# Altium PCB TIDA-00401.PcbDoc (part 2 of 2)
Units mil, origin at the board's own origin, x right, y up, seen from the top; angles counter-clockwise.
Board outline 3543.31 x 2362.2 mil, 2 copper layers (Top Layer, Bottom Layer), stack 62 mil thick; 132 components, 43 nets, 274 pads, 44 vias.
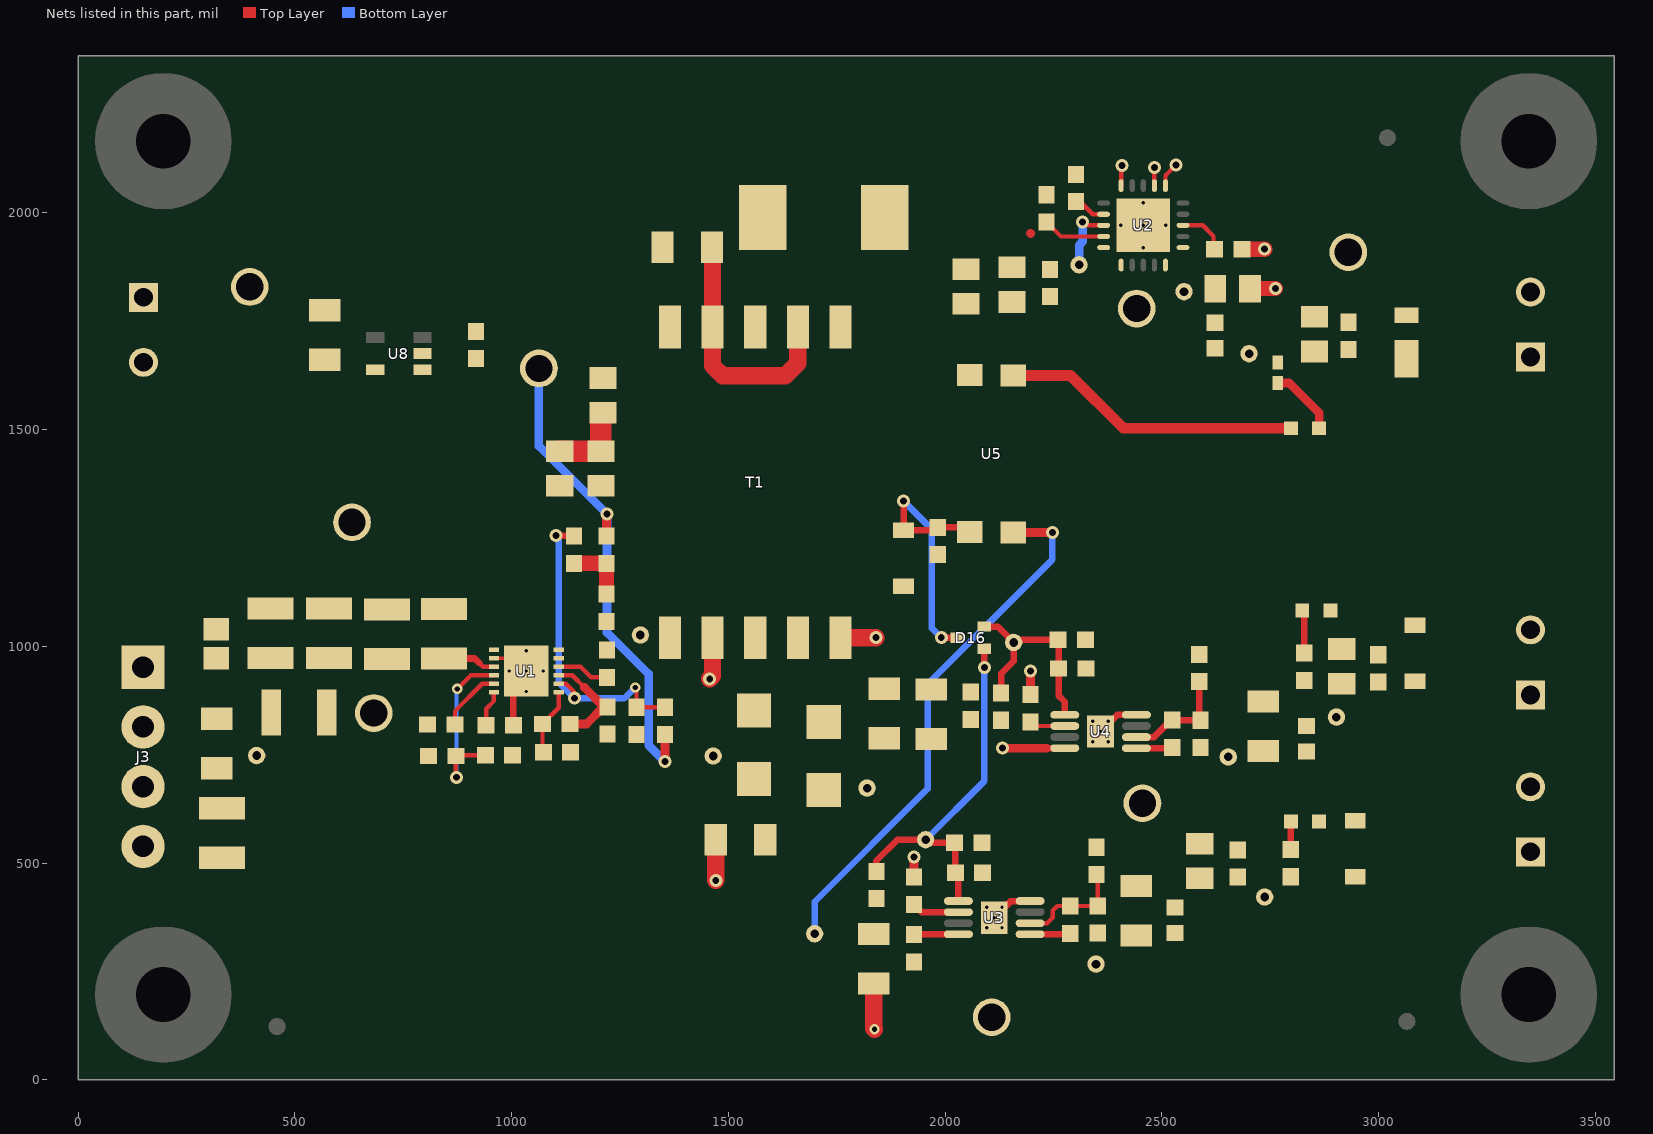
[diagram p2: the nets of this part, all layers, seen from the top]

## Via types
v1: diameter 30, hole 16, Top Layer to Bottom Layer, tented both sides, 21 vias
v2: diameter 19.68, hole 7.87, Top Layer to Bottom Layer, tented both sides, 20 vias
v3: diameter 24, hole 12, Top Layer to Bottom Layer, tented both sides, 3 vias

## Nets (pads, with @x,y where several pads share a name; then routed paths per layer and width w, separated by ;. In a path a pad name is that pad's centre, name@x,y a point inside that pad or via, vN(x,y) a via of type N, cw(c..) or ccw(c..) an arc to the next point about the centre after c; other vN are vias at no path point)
9V_NON_ISO: C6.2 C47.1 R5.2 R7.2 T1.10 TP11.1 U8.1 | length 1141
  Top Layer w20: C6.2@1219,1254.5 1219,1299 1220,1300 v1(1220,1305) ; v1(1354,734) R7.2@1354,796.5
  Bottom Layer w20: TP11.1@1063,1641 1063,1462 v1(1220,1305) 1220,1032 1316,936 1316,772 v1(1354,734)
15GND: C1.1 C2.1 C27.1 C28.1 C29.2 C30.1 C31.2 C32.2 C33.2 C35.1 C36.1 C37.2 C38.1 C39.2 C40.2 C41.2 D6.2 D7.1 D8.1 D9.2 D15.2 J5.2 J6.2 R15.2 R16.1 R20.2 R26.2 R27.1 T1.2 T1.5 TP2.1 TP4.1 TP5.1 U3.4 U3.9 U4.4 U4.9 | length 677.2
  Top Layer w15: v2(2113.32,374.2) 2151.71,412.59 U3.4@2196,412.59 ; v2(2358.54,803.49) 2396.93,841.88 U4.4@2441.22,841.88
  Top Layer w20: C33.2@1928,467.5 v1(1928,514) ; C41.2@2197,888.5 v1(2197,943)
  Top Layer w40: v1(1457,925) 1463.43,931.43 T1.2@1463.43,1020 ; v1(1470.91,460.09) C1.1@1470.91,554 ; T1.5@1758.7,1020 v1(1840,1020) ; C31.2@1835.32,222.43 1835.32,118.68 v3(1837,117)
  other v2: 2095.61,350.58 2131.04,350.58 2095.61,397.83 2131.04,397.83 2340.83,779.87 2376.26,779.87 2340.83,827.11 2376.26,827.11
+5V_ISO: C21.1 C45.2 D24.1 J4.1 L2.2 R21.1 TP16.1
+6V_ISO: C4.1 C44.1 C46.2 D3.1 TP6.1 U2.13 U2.15 U2.16 | length 154.1
  Top Layer w10: v1(2317,1979) 2325,1971 U2.13@2365.46,1971
  Bottom Layer w20: TP6.1@2309,1880 2309,1925 2317,1933 v1(2317,1979)
+15V_ISO: C27.2 C28.2 D6.1 J5.1 L3.2 R14.1 TP17.1
+18V_ISO: C1.2 C30.2 C31.1 D1.1 R23.2 TP1.1 U3.8 U5.4 | length 1345.6
  Top Layer w10: C30.2@1928.32,335.02 C30.2@1929.13,335.82
  Top Layer w15: C30.2@1929.13,335.82 U3.8@2030.65,335.82
  Top Layer w20: U5.4@2157,1262.41 v1(2247.41,1262.41)
  Bottom Layer w15: TP1.1@1699,337 1699,411 1960,672 1960,913 2247.41,1200.41 v1(2247.41,1262.41)
+24VDC: C16.1 C17.1 F1.1 L1.1 RV1.2 TP14.1
-15V_ISO: C35.2 C36.2 D8.2 J6.1 L4.2 R24.1 TP22.1
-18V_ISO: C2.2 C38.2 C39.1 D2.2 R17.2 TP3.1 U4.8 | length 144
  Top Layer w15: 2234.57,765.11 U4.8@2275.87,765.11
  Top Layer w20: v1(2131.89,765.11) 2234.57,765.11
BST: C5.2 U1.10 | length 121.5
  Top Layer w10: U1.10@1108.8,952.84 1159.16,952.84 1183.58,928.42 C5.2@1220.2,928.42
"CO PRI": C14.1 C15.1 R5.1 | length 186.1
  Top Layer w50: C15.1@1111,1450 C14.1@1206,1450 1206,1534 R5.1@1211,1539
EN: R3.1 R9.2 U1.4 | length 420.4
  Top Layer w10: v1(873,698) 871.5,699.5 R3.1@871.5,747 873.5,749 R9.2@939.5,749 ; v3(874.68,901.72) 906.12,933.16 U1.4@959.2,933.16
  Bottom Layer w10: v1(873,698) 873,900.04 v3(874.68,901.72)
EN_15V: C29.1 D16.1 R23.1 R27.2 TP26.1 U3.5 | length 862.3
  Top Layer w15: R23.1@1841.32,481.02 1841.32,505.32 1890,554 TP26.1@1955,554 1962,547 C29.1@2021.5,547 2023.5,545 R27.2@2023.5,478 2030.65,470.86 U3.5@2030.65,412.59 ; v1(2090.5,951.5) D16.1@2090.5,994.41
  Bottom Layer w15: TP26.1@1955,554 2090.5,689.5 v1(2090.5,951.5)
EN_-15V: C37.1 D16.2 R16.2 R17.1 TP25.1 U4.5 | length 495.7
  Top Layer w15: D16.2@2090.5,1045.59 2121.41,1045.59 TP25.1@2158,1009 ; R17.1@2129,892.5 2129,937 2158,966 TP25.1@2158,1009 ; U4.5@2275.87,841.88 2275.87,872.13 2261.5,886.5 R16.2@2261.5,949 2261.5,1014 C37.1@2260.5,1015 2164,1015 TP25.1@2158,1009
FB: C8.2 R7.1 R8.2 U1.8 | length 753.3
  Top Layer w10: U1.8@1108.8,913.47 1125.65,913.47 1144,895.12 1144,880.92 v1(1144.61,880.3) ; v3(1285,905) 1288,902 R8.2@1288,859.5 R7.1@1354,859.5
  Top Layer w15: v1@1103.5,1254.5 C8.2@1144,1254.5
  Bottom Layer w15: v1@1099,1253 1109,1243 1109,915.92 v1(1144.61,880.3) 1260.3,880.3 v3(1285,905)
  other v1: 1102,1256
FPWM: R4.2 R10.2 U1.7 | length 154.3
  Top Layer w10: R10.2@1073.31,755.84 1071.31,757.84 R4.2@1071.31,820.84 1108.8,858.34 U1.7@1108.8,893.79
GND: C3.2 C7.2 C11.2 C12.2 C13.2 C14.2 C15.2 C16.2 C17.2 C18.2 C42.1 C47.2 J2.1 J3.1 J3.2 R8.1 R9.1 R10.1 RV1.1 TP12.1 TP13.1 U1.1 U1.2 U1.13 U8.2 | length 224.5
  Top Layer w8: U1.2@959.2,972.53 1004.47,972.53 v2(1034,943)
  Top Layer w15: C7.2@1004.3,817.84 1004.3,913.3 v2(1034,943)
  other v2: 1034,895.76 994.63,943 1073.37,943 1034,990.24
NetC19_2: C19.2 C20.1 L2.1 TP15.1 U2.1 U2.3 U2.20 | length 111.9
  Top Layer w10: U2.3@2548.54,1971 2594,1971 2619,1946 2619,1918.5 C19.2@2621.5,1916
NetC25_1: C25.1 U2.14 | length 145.2
  Top Layer w10: C25.1@2234,1978.5 2267.09,1945.41 U2.14@2365.46,1945.41
NetC26_1: C26.1 C32.1 L3.1 R25.1 TP18.1 U3.1 | length 93.2
  Top Layer w15: U3.1@2196,335.82 2286.12,335.82 C26.1@2288.32,338.02
NetC26_2: C26.2 R25.2 R26.1 U3.2 | length 271.7
  Top Layer w10: U3.2@2196,361.41 2235.21,361.41 2248.32,374.52 2248.32,390.79 2258.55,401.02 C26.2@2288.32,401.02 R25.2@2343.48,401.02 ; R26.1@2349,473.5 2352,470.5 R26.1@2352,459.5 ; R26.1@2351,460.5 R26.1@2352,459.5 ; R25.2@2353,391.5 R25.2@2343.48,401.02 ; R26.1@2353,458.5 R26.1@2352,459.5 ; R25.2@2343.48,401.02 2351.52,401.02 R25.2@2352,401.5 R26.1@2352,459.5
NetC33_1: C33.1 U3.6 | length 109.9
  Top Layer w15: C33.1@1928,404.5 1945.5,387 U3.6@2030.65,387
NetC34_1: C34.1 C40.1 L4.1 R19.1 TP20.1 U4.1 | length 83.1
  Top Layer w15: U4.1@2441.22,765.11 2521.66,765.11 C34.1@2523.54,766.99
NetC34_2: C34.2 R19.2 R20.1 U4.2 | length 253.8
  Top Layer w15: U4.2@2441.22,790.7 2481.7,790.7 2520.98,829.98 C34.2@2523.54,829.98 R19.2@2588.51,829.98 ; R20.1@2586,918.5 2586,832.5 R19.2@2588.51,829.98 ; R19.2@2589,829.5 R19.2@2588.51,829.98
NetC41_1: C41.1 U4.6 | length 82.7
  Top Layer w10: C41.1@2197,825.5 2206.22,816.29 U4.6@2275.87,816.29
NetC42_2: C42.2 J2.2 U8.5
NetD1_2: D1.2 T1.3
NetD2_1: D2.1 T1.4
NetD3_2: D3.2 T1.6 T1.8
NetD5_1: D5.1 U5.1 | length 690.9
  Top Layer w25: U5.1@2157,1624.61 2289.39,1624.61 2411,1503 D5.1@2797.52,1503
NetD5_2: D5.2 R21.2 | length 159.7
  Top Layer w20: R21.2@2767,1607.38 2793.94,1607.38 2862.48,1538.84 D5.2@2862.48,1503
NetD7_2: D7.2 R14.2 | length 65.1
  Top Layer w15: R14.2@2797,531.5 2797,594.48 D7.2@2798.52,596
NetD9_1: D9.1 R24.2 | length 100.4
  Top Layer w15: D9.1@2823.52,1083 2828,1078.52 R24.2@2828,984.5
NetD15_1: D15.1 D16.3 R15.1 U5.3 | length 615.6
  Top Layer w15: v1(1904,1335) D15.1@1904,1267.47 1975.97,1267.47 R15.1@1983,1274.5 2045.89,1274.5 U5.3@2057,1263.39 ; v1(1991,1020) D16.3@2027.5,1020
  Bottom Layer w15: v1(1904,1335) 1969.5,1269.5 1969.5,1041.5 v1(1991,1020)
NetF1_2: F1.2 J3.3 J3.4
NetR22_1: R22.1 U2.12 | length 75.4
  Top Layer w10: R22.1@2302,2025.5 2311.51,2025.5 2340.42,1996.59 U2.12@2365.46,1996.59
RON: R2.1 U1.5 | length 146.3
  Top Layer w10: R2.1@869.5,820 869.5,850.5 932.47,913.47 U1.5@959.2,913.47
SGND: C3.1 C4.2 C19.1 C20.2 C21.2 C25.2 C44.2 C45.1 C46.1 D24.2 J4.2 R22.2 T1.7 T1.9 TP7.1 TP8.1 U2.6 U2.7 U2.10 U2.21 U5.2 | length 833.8
  Top Layer w10: U2.10@2405.82,2062.54 2405.82,2106.82 v1(2408,2109) ; U2.7@2482.59,2062.54 v1(2482.59,2104.41) ; U2.6@2508.18,2062.54 2508.18,2086.18 v1(2532,2110)
  Top Layer w20: 2197,1952.5 2197.5,1952
  Top Layer w35: C19.1@2684.5,1916 v1(2737,1916) ; C20.2@2703,1825 v1(2762,1825)
  Top Layer w40: C3.1@1462.09,1920 1463.43,1918.66 T1.9@1463.43,1736.54 1463.43,1647.57 1487,1624 1631,1624 1660.28,1653.28 T1.7@1660.28,1736.54
  other v2: 2457,1918.83 2404.83,1971 2457,1971 2509.17,1971 2457,2023.17
SS: C7.1 U1.6 | length 83.4
  Top Layer w10: C7.1@941.31,817.84 941.31,855.95 959.2,873.84 U1.6@959.2,893.79
VCC: C13.1 R4.1 U1.9 | length 228.4
  Top Layer w10: U1.9@1108.8,933.16 1139.84,933.16 1168,905
  Top Layer w20: R4.1@1134.3,820.84 1172.85,820.84 1212.5,860.5 1168,905
VIN: C11.1 C12.1 C18.1 L1.2 R2.2 R3.2 TP10.1 U1.3 | length 123.1
  Top Layer w10: 926,961 934.16,952.84 U1.3@959.2,952.84
  Top Layer w15: C12.1@844,971.91 915.09,971.91 926,961
VRIPL: C6.1 C8.1 R6.2 | length 146
  Top Layer w35: C8.1@1144,1191.5 C6.1@1219,1191.5 R6.2@1219,1120.5
"VSW PRI": C5.1 R6.1 T1.1 TP9.1 U1.11 U1.12
pads on no net: FID1.1 FID2.1 FID3.1 H1.1 H2.1 H3.1 H4.1 LBL1.0 U2.2 U2.4 U2.5 U2.8 U2.9 U2.11 U2.17 U2.18 U2.19 U3.3 U3.7 U4.3 U4.7 U8.3 U8.4

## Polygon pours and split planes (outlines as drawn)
-15V_ISO on Top Layer "Top Layer--15V_ISO" (solid, remove dead copper, pour order 49): 2798,936 2798,814 2814,798 2937,798 2976,837 3394,837 3404,847 3404,934 3397,941 2803,941
NetC42_2 on Top Layer "Top Layer-NetC42_2" (solid, remove dead copper, pour order 31): 99.5,1683 100,1634 108,1625 704,1625 706,1627 706,1691 704,1693 109.5,1693
9V_NON_ISO on Top Layer "Top Layer-VIN" (solid, remove dead copper, pour order 54): 775,1651 773,1649 773,1628 775,1626 836,1626 868,1594 1375,1594 1394,1613 1394,1784 1392,1786 1339,1786 1336,1783 1336,1697 1323,1684 869,1684 836,1651
NetD2_1 on Top Layer "Top Layer-NetD2_1" (solid, remove dead copper, pour order 41): 1635,1068 1635,823 1672,786 1777,786 1796,805 1796,899 1763,932 1695,932 1686,941 1686,1068 1684,1070 1637,1070
NetD1_2 on Top Layer "Top Layer-NetD1_2" (solid, remove dead copper, pour order 40): 1536,1068 1536,919 1510,893 1510,818 1520,808 1610,808 1616,814 1616,881 1595,902 1595,964 1587,973 1587,1068 1585,1070 1538,1070
"VSW PRI" on Top Layer "Top Layer-VSW PRI" (solid, remove dead copper, pour order 32): 1155,1000 1185,1030 1185,1069 1193,1077 1302,1077 1309,1070 1389,1070 1391,1068 1391,969 1390,968 1256,968 1252,972 1127,972 1122,967 1096,967 1095,968 1095,999 1096,1000
NetD3_2 on Top Layer "Top Layer-NetD3_2" (solid, remove dead copper, pour order 38): 1526,2078 1524,2076 1524,1912 1537,1899 1537,1830 1536,1829 1536,1689 1538,1687 1586,1687 1588,1689 1588,1833 1605,1850 1729,1850 1732,1847 1732,1692 1736,1688 1783,1688 1785,1690 1785,1871 1740,1916 1662,1916 1650,1928 1650,2060 1632,2078
GND on Top Layer "Bottom Layer-No Net" (solid, remove dead copper, pour order 28): 1357,1869 1373.78,1885.83 1373.78,2006.26 1352.28,2027.76 1198.28,2027.76 1178.78,2008.26 1178.78,1901.26 1211,1869
NetD5_1 on Top Layer "Top Layer-NetD5_1" (solid, remove dead copper, pour order 45): 2128,1650 2127,1649 2127,1600 2141,1586 2236,1586 2251,1601 2251,1636 2247,1640 2193,1640 2183,1650
NetF1_2 on Top Layer "Top Layer-NetF1_2" (solid, remove dead copper, pour order 46): 117,733 186,733 197,722 210,709 210,592 210,571 219,562 220,561 306,561 390,561 394,557 396.72,554.28 396.72,500.8 396.72,500.72 396.72,496.72 382,482 378.32,478.32 150,478.32 111.68,478.32 101,489 94,496 94,580 94,725 102,733
+24VDC on Top Layer "Top Layer-+24VDC" (solid, remove dead copper, pour order 52): 289,997 290,998 363,998 492,998 496,994 496,968 496,894.99 487,885.99 487,816 487,773 481,767 434,720 434,649 391,606 386,601 364,601 278,601 272,607 263.28,615.72 263.28,628.49 263.28,641.28 263.28,724.28 283,744 284,745 356,745 365,754 371,760 371,860 372,861 349,884 309,884 295,898 283,910 283,991
VIN on Top Layer "Top Layer-VIN 1" (solid, remove dead copper, pour order 53): 525,995 525,949 551,923 551,801 562,790 632,790 696,726 822,726 828,732 828,933 842,947 904,947 917,960 917,987 907,997 527,997
+18V_ISO on Top Layer "Bottom Layer-+18V_ISO" (solid, remove dead copper, pour order 43): 1598,734 1607,725 1607,615 1621,601 1621,519 1703,437 1870,437 1873,434 1873,391 1908,356 1949,356 1954,351 1954,317 1952,315 1876,315 1872,311 1583,311 1560,334 1560,589 1510,639 1510,731 1513,734
-18V_ISO on Top Layer "Top Layer--18V_ISO" (solid, remove dead copper, pour order 42): 1669,624 1673,620 1852,620 1857,625 1857,734 1863,740 2149,740 2151,742 2151,845 2146,850 1822,850 1812,840 1812,795 1778,761 1778,726 1759,707 1676,707 1669,700
NetC34_1 on Top Layer "Top Layer-NetC34_1" (solid, remove dead copper, pour order 50): 2493,771 2504,782 2677,782 2685,790 2762,790 2776,776 2855,776 2859,772 2859,726 2854,720 2498,720 2493,725
NetC26_1 on Top Layer "Top Layer-NetC26_1" (solid, remove dead copper, pour order 44): 2271,359 2256,344 2256,329 2278,307 2278,260 2287,251 2377,251 2382,256 2382,308 2384,311 2477,311 2486,320 2550,320 2552,322 2552,357 2550,359 2373,359 2365,351 2313,351 2305,359
+5V_ISO on Top Layer "Top Layer-+5V_ISO" (solid, remove dead copper, pour order 48): 2568,1644 2576,1636 2793,1636 2816,1613 3392,1613 3397,1620 3397,1701 3387,1706 2576,1706 2568,1698
+6V_ISO on Top Layer "Top Layer-+6V_ISO" (solid, remove dead copper, pour order 39): 1952,2080 1957,2075 1957,1931 1963,1925 2379,1925 2380,1924 2380,1911 2398,1893 2409,1893 2412,1890 2412,1868 2393,1849 1816,1849 1805,1860 1805,2074 1811,2080
+15V_ISO on Top Layer "Top Layer-+15V_ISO" (solid, remove dead copper, pour order 51): 2482,382 2484,380 3396,380 3405,389 3405,578 3391,592 3128,592 3024,488 2515,488 2482,455
NetC19_2 on Top Layer "Top Layer-NetC19_2" (solid, remove dead copper, pour order 47): 2588,1926 2600,1938 2638,1938 2641,1935 2641,1863 2648,1856 2648,1734 2641,1727 2513,1727 2502,1736 2502,1891 2505,1894 2525,1894 2534,1903 2534,1924 2536,1926
15GND on Top Layer "Top Layer-15GND" (solid, remove dead copper, pour order 35): 1431.24,1101 1430.19,93 1430.19,46 1438.19,39 3433.19,38 3518.19,38 3529.19,52 3529.19,1319 3495.19,1339 1436,1339 1431,1334 1431,1216
SGND on Top Layer "Top Layer-SGND" (solid, remove dead copper, pour order 37): 1456,1601 1443,1613 1443,2328 1471,2357 3271,2358 3511,2358 3540,2330 3541,1492 3532,1482 2560,1482 2413,1590 1471,1590
GND on Top Layer "Top Layer-GND" (solid, remove dead copper, pour order 30): 1375.7,1830.65 1375.7,2327.65 1351.7,2341.65 32.7,2341.65 14.7,2313.65 14.7,347.65 15.7,200.65 15.7,104.65 14.7,62.65 14.7,28.65 15.7,12.65 36.7,0.65 1362.7,0.65 1380.7,21.65 1380.7,1825.65
GND on Bottom Layer "Bottom Layer-GND" (solid, remove dead copper, pour order 29): 1375,1840.65 1375,2337.65 1351,2351.65 32,2351.65 14,2323.65 14,357.65 15,210.65 15,114.65 14,72.65 14,38.65 15,22.65 36,10.65 1362,10.65 1380,31.65 1380,1835.65
15GND on Bottom Layer "Bottom Layer-15GND" (solid, remove dead copper, pour order 34): 1434.24,1101 1433.19,93 1433.19,46 1441.19,39 3436.19,38 3521.19,38 3532.19,52 3532.19,1319 3498.19,1339 1439,1339 1434,1334 1434,1216
SGND on Bottom Layer "Bottom Layer-SGND" (solid, remove dead copper, pour order 36): 1458,1601 1445,1613 1445,2328 1473,2357 3273,2358 3513,2358 3542,2330 3543,1492 3534,1482 2562,1482 2415,1590 1473,1590
15GND on Bottom Layer "Bottom Layer-15GND 1" (solid, remove dead copper, pour order 33): 1431.24,1101 1430.19,93 1430.19,46 1438.19,39 3433.19,38 3518.19,38 3529.19,52 3529.19,1319 3495.19,1339 1436,1339 1431,1334 1431,1216

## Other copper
Top Layer:
  pour cut-out: 420,617 420,322 419,321 331,321 331,465 332.22,466.22 401.22,466.22 410,475 410,617
  pour cut-out: 1849,1339 1850,1338 1850,1097 1873,1097 1873,1058 1793,1058 1794,1079.06 1614,1081 1526.26,1079.21 1481,1078 1457,1078 1444,1079.06 1435.32,1079.06 1428,1085 1428,1341 1847.25,1341 1849.25,1339
  pour cut-out: 2007.25,1737.88 2006.75,1730.12 2006.75,1590 1970.75,1590 1970.75,1738.12
  pour cut-out: 35.3,754.5 35.8,755 274,755 274,733 35.3,733.65
  pour cut-out: 1445,1977 1512,1977 1512,2035 1511.5,2063 1511.76,2076 1510,2086 1512,2091 1516.5,2091.5 1529,2092 1888,2092 1888,2327 1445.3,2327 1445,2326.7
  pour cut-out: 35,1169 377.7,1169 377.7,1120 35,1120
  text "©" at 496,240 h35
  text "2015" at 546,240 h35
  text "TI" at 693,240 h35
  text ".Layer_Name" at 577,-858.49 h35
Bottom Layer:
  pour cut-out: 1849,1339 1850,1338 1850,1097 1873,1097 1873,1058 1793,1058 1793,1091 1434,1091 1428,1097 1428,1341 1847.25,1341 1849.25,1339
  pour cut-out: 520,280 520,220 1381,220 1381,280
  pour cut-out: 35.3,761.15 46,762 888.29,759.29 987,758 987,717 889.6,716.98 791,717 489,717 448.65,717.35 448,718 278.46,718 259.08,737.38 35.3,737.38
  pour cut-out: 2076,2327 2076,1590 2075,1591 1445,1591 1445,2326.7 1445.3,2327
  pour cut-out: 35,1169 377.7,1169 377.7,1120 35,1120
  text ".VersionControl_RevNumber" at 1214,232 h35
  text "SVN:" at 1358,232 h35
  text "MADE IN U.S." at 1374,90 h35
  text "UL94V-0" at 1668,83 h35
  text ".Layer_Name" at 577,-858.49 h35

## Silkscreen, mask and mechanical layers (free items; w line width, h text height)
Top Overlay:
  circle w6: c2576.92,1922 r6
  circle w6: c2240,311 r6
  circle w6: c2476,743 r6
  circle w6: c930.8,991.84 r6
  lines w6: 765,701 765,850 765,863 780,863 ; 766,700 785,700 ; 772,685 772,639 ; 784,481 763,481 763,607 763,615 784,615 ; 1032,478 1053,478 1053,486 1053,612 1032,612 ; 1122,1134 1122,1143 1132,1133 1121,1133 1136,1148 1150,1148 ; 1135,1318 1073,1318 1053,1298 ; 1156,859 1175,859 ; 1161,696 1176,696 1176,709 1176,858 ; 1314,785 1314,789 ; 2320,294 2314,294 2299,279 ; 772,639 763,648 781,648 772,639 ; 1053,1298 1053,1311 1066,1298 1053,1298 ; 2299,279 2299,289 2309,279 2299,279
  lines w8: 1271,996 1270,996 1264,990 1264,950 1279,935 1384,935 1409,910 1395,910 1411,926 1411,912 ; 1893.84,532.6 1902,524.44 1902,511 ; 2825,1428 2854,1428 2882,1400 2882,1448 2882,1458 2854,1430 ; 2852,1404 2852,1449 ; 2883,1428 2920,1428 ; 2934,867 2951,850 2961,850
  text ".Layer_Name" at 577,-858.49 h35
Bottom Overlay:
  text ".Layer_Name" at 577,-858.49 h35
Top Paste:
  text ".Layer_Name" at 577,-858.49 h35
Bottom Paste:
  text ".Layer_Name" at 577,-858.49 h35
Top Solder:
  text ".Layer_Name" at 581,-865 h35
Bottom Solder:
  text ".Layer_Name" at 577,-858.49 h35
Drill Guide:
  text ".Layer_Name" at 577,-858.49 h35
M1 Board Outline:
  the board outline again, w10
M2 Board Dimensions:
  rectangle: 0,-285.5 125,-160.5
  rectangle: 125,-410.5 500,-285.5
  lines w7: 0,-285.5 1000,-285.5 ; 125,-410.5 125,-160.5 ; 250,-410.5 250,-160.5 ; 500,-410.5 500,-160.5 ; 750,-410.5 750,-160.5 ; 0,-410.5 1000,-410.5 1000,-160.5 0,-160.5 0,-410.5
M3 3D STEP Top:
  text ".Layer_Name" at 577,-858.49 h35
M4 3D STEP Bottom:
  text ".Layer_Name" at 577,-858.49 h35
M5 Assembly Top:
  circle w6: c231.61,971 r5.39
  lines w5: 1095,261 1695,261
  lines w8: 2824,1149 2857,1149 2879,1171 2879,1125 2857,1147 ; 2826,1437 2856,1437 2876,1457 2876,1414 2856,1434 ; 2852,1409 2852,1460 ; 2854,1127 2854,1170 ; 2877,1437 2906,1437 ; 2882,1148 2913,1148
  lines w10: -292,-930.17 6308,-930.17 ; -292,-726.83 6310,-726.83 ; -292,-523.5 -292,-1133.5 3713,-1133.5 6310,-1133.5 6310,-523.5 -291.5,-523.5 -291.5,-1133.5 1284,-1133.5 ; 2173,-1133.5 2173,-523.5 ; 3440,-726.83 3440,-523.5 ; 4280,-726.83 4280,-523.5 ; 4902,-1140 4902,-937.17
  text "COMPONENTS MARKED 'DNP' SHOULD NOT BE POPULATED." at 1153.5,-318.5 h35
  text "ASSEMBLY VARIANT:" at 1153,-434 h35
  text ".VariantName" at 2189,-434 h35
  text "PCB VIEWED FROM TOP SIDE" at -228.5,-655.67 h35
  text "BOARD #:" at 2248,-655.67 h35
  text ".PRJ_Number" at 2793.5,-655.67 h35
  text "REV:" at 3638,-655.67 h35
  text ".PCB_Rev" at 3929.5,-655.67 h35
  text "SVN REV:" at 4476,-655.67 h35
  text ".VersionControl_RevNumber" at 4982,-655.67 h35
  text "E1" at 3790,-665 h40
  text "IGNORE ->" at -228.5,-858.49 h35
  text "ASSEMBLY TOP" at 352,-869 h35
  text "PLOT NAME =" at -228.5,-1064.34 h35
  text ".plot_File_Name" at 577,-1064.34 h35
  text "GENERATED    :" at 2250,-1064.34 h35
  text ".Print_Date" at 3119.5,-1064.34 h35
  text ".Print_Time" at 3848.5,-1064.34 h35
  text "TEXAS INSTRUMENTS" at 5113,-1064.34 h35
M6 Assembly Bottom:
  lines w10: -292.5,-727.33 6309.5,-727.33 ; -290.5,-930.67 6309.5,-930.67 ; 1115.5,-1140.5 1115.5,-937.67 ; 1737.5,-727.33 1737.5,-524 ; 2577.5,-727.33 2577.5,-524 ; 3844.5,-1134 3844.5,-524 ; 4733.5,-1134 6309,-1134 6309,-524 -292.5,-524 -292.5,-1134 2304.5,-1134 6309.5,-1134 6309.5,-524
  text "COMPONENTS MARKED 'DNP' SHOULD NOT BE POPULATED." at 6102,-318 h35
  text ".VariantName" at 5058,-434 h35
  text "ASSEMBLY VARIANT:" at 6097,-434 h35
  text ".VersionControl_RevNumber" at 1035.5,-656.17 h35
  text "SVN REV:" at 1541.5,-656.17 h35
  text ".PCB_Rev" at 2088,-656.17 h35
  text "REV:" at 2379.5,-656.17 h35
  text ".PRJ_Number" at 3224,-656.17 h35
  text "BOARD #:" at 3769.5,-656.17 h35
  text "PCB VIEWED FROM BOTTOM SIDE" at 6246,-656.17 h35
  text "E1" at 2230,-663 h40
  text "IGNORE ->" at 2547.85,-858.49 h35
  text "ASSEMBLY BOTTOM" at 882,-872 h35
  text "TEXAS INSTRUMENTS" at 904.5,-1064.84 h35
  text ".Print_Time" at 2169,-1064.84 h35
  text ".Print_Date" at 2898,-1064.84 h35
  text "GENERATED    :" at 3767.5,-1064.84 h35
  text ".plot_File_Name" at 5440.5,-1064.84 h35
  text "PLOT NAME =" at 6246,-1064.84 h35
M7 LPKF Text Top:
  text "PMP10545" at 629,2271 h35
M9 Title Sheet:
  drawing of 57 lines, arcs and shapes, not listed
  text "1" at 739.84,8036.5 h35
  text "2" at 3235.5,8036.5 h35
  text "3" at 5724.84,8036.5 h35
  text "4" at 8231.51,8036.5 h35
  text "5" at 10730.5,8036.5 h35
  text "6" at 13235.5,8036.5 h35
  text "A" at -416.5,6893.5 h35
  text "A" at 14383.5,6893.5 h35
  text "B" at -416.5,4513.5 h35
  text "B" at 14383.5,4513.5 h35
  text "C" at -416.5,2138.5 h35
  text "C" at 14383.5,2138.5 h35
  text "PROJECT TITLE:" at 11343.5,277.5 h35
  text "TIDA-0O401" at 11393.5,144.17 h35
  text "DESIGNED FOR:" at 11343.5,-23.5 h35
  text ".PRJ_Customer" at 11393.5,-163.5 h35
  text "D" at -416.5,-231.5 h35
  text "D" at 14383.5,-231.5 h35
  text "FILE NAME:" at 11343.5,-323.5 h35
  text ".PCB_File_Name_No_Path" at 11393.5,-443.5 h35
  text "Texas Instruments (TI) and/or its licensors do not warrant the accuracy or completeness of this specification" at 6374,-605.34 h35
  text "ENGINEER:" at 11343.5,-613.5 h35
  text "LAYOUT BY:" at 12848.5,-613.5 h35
  text "or any information contained therein. TI and/or its licensors do not warrant that this design will meet" at 6329.01,-718 h35
  text ".PRJ_Engineer" at 11393.5,-768.49 h35
  text ".PCB_Layout" at 12899,-768.49 h35
  text "the specifications, will be suitable for your application or fit for any particular purpose, or will operate in" at 6329.01,-830.67 h35
  text "ALTIUM DESIGNER VERSION:" at 12848.5,-923.5 h35
  text "an implementation. TI and/or its licensors do not warrant that the design is production worthy. You should" at 6329.01,-943.33 h35
  text "completely validate and test your design implementation to confirm the system functionality for your application." at 6374,-1056 h35
  text ".print_Scale" at 11393.5,-1056.83 h35
  text ".Application_BuildNumber" at 12899,-1056.83 h35
  text "1" at 739.84,-1263.5 h35
  text "2" at 3235.5,-1263.5 h35
  text "3" at 5724.84,-1263.5 h35
  text "4" at 8231.51,-1263.5 h35
  text "5" at 10730.5,-1263.5 h35
  text "6" at 13235.5,-1263.5 h35
M10 Fab Notes:
  drawing of 191 lines, arcs and shapes, not listed
  text "DESIGN INFORMATION" at 12386.02,6690 h35
  text "(REFER ALSO ARRAY/PANEL PROFILING INFORMATION)" at 12024.46,6528.29 h35
  text "BOARD SIZE" at 11338.46,6524 h35
  text "X" at 12306.46,6396.18 h35
  text "60MM" at 12606,6394 h35
  text "90MM" at 11930.59,6390.18 h35
  text "Number of Layers :" at 11756.46,6289 h35
  text "2" at 12851.27,6279 h35
  text "MIN. TRACK WIDTH:" at 11756.46,6150 h35
  text "8" at 12852.7,6150 h35
  text "MIL" at 13007.46,6150 h35
  text "7.87" at 12757,6021 h35
  text "MIN. CLEARANCE:" at 11756.46,6018 h35
  text "MIL" at 13007.46,6018 h35
  text "MIL" at 13173,5891 h35
  text "MIN. VIA PAD SIZE:" at 11756.46,5886 h35
  text "19.685" at 12822.71,5886 h35
  text "0.152mm (6MIL)" at 12451.46,5744.29 h35
  text "EXTERNAL" at 13202,5742 h35
  text "MINIMUM ANNULAR RING" at 11427.23,5740 h35
  text "PER" at 11627.23,5622 h35
  text "IPC-D-275 CLASS 2 LEVEL C" at 11847.23,5622 h35
  text "MIL, HOLES" at 13335.46,5509.71 h35
  text "+/-" at 12943,5509 h35
  text "+/-" at 13797,5509 h35
  text "REGISTRATION TOLERANCES:" at 11427.23,5504 h35
  text "METAL" at 12627,5504 h35
  text "5" at 13203.2,5504 h35
  text "3" at 14036.2,5504 h35
  text "MIL" at 14152.46,5504 h35
  text "IMPEDENCE CONTROLLED BOARD:NO" at 11460,5355 h35
  text "MATERIAL:" at 11336.46,5131.54 h35
  text "X" at 11609,5002 h35
  text "FR-4 High Tg" at 12322.9,4991.21 h35
  text "FR-408" at 11757.46,4982.64 h35
  text "OTHER" at 13245.46,4982.64 h35
  text "62.99 MIL (1.6mm) +/-10%" at 12077.56,4819.92 h35
  text "THICKNESS:" at 11411.23,4815.64 h35
  text "X" at 11949.4,4815.64 h35
  text "OTHER" at 13362.46,4815.64 h35
  text "TOLERANCE:" at 11411.23,4657.64 h35
  text "X" at 12250.53,4657.64 h35
  text "ANSI IPC-6012 TYPE 3 CLASS 2" at 12437.48,4657.64 h35
  text "OTHER +/-" at 12437.46,4501.64 h35
  text "BOW & TWIST:" at 11411.23,4344.64 h35
  text "X" at 12250.53,4344.64 h35
  text "ANSI IPC-6012 TYPE 3 CLASS 2" at 12437.48,4344.64 h35
  text "OTHER +/-" at 12437.46,4186.13 h35
  text "DRILLING:" at 11336.46,4047.64 h35
  text "REFERENCE:" at 11411.23,3930.64 h35
  text "X" at 12059.46,3930.64 h35
  text "AS SHOWN" at 12246.46,3930.64 h35
  text "X" at 12960.46,3930.64 h35
  text "NC_DRILL FILES" at 13097.46,3930.64 h35
  text "PTH MIN COPPER THICKNESS:" at 11411.23,3772.64 h35
  text "X" at 12761.46,3772.64 h35
  text "1MIL" at 12898.46,3772.64 h35
  text "OTHER" at 13395.46,3772.64 h35
  text "BOARD FINISH:" at 11336.46,3613.64 h35
  text "SILKSCREEN:" at 11491.68,3495.64 h35
  text "X" at 12440.46,3495.64 h35
  text "TOP" at 12566.46,3495.64 h35
  text "X" at 12950.46,3495.64 h35
  text "BOTTOM" at 13077.46,3495.64 h35
  text "SILKSCREEN COLOR:" at 11491.68,3328.64 h35
  text "X" at 12439.42,3328.64 h35
  text "WHITE" at 12566.46,3328.64 h35
  text "OTHER" at 13077.46,3328.64 h35
  text "SOLDER RESIST COLOR:" at 11491.68,3158.64 h35
  text "X" at 12059.42,2999.44 h35
  text "GREEN" at 12186.46,2999.44 h35
  text "BLUE" at 12777.46,2999.44 h35
  text "OTHER" at 13315.46,2999.44 h35
  text "IMMERSION GOLD (ENIG)" at 12397.46,2810.92 h35
  text "ENEPIG" at 13735,2807.64 h35
  text "SURFACE FINISH:" at 11336.46,2806.64 h35
  text "X" at 12210.51,2806.64 h35
  text "IMM. TIN/SILVER OR EQUIV" at 11666,2649.64 h35
  text "OTHER" at 13097.46,2649.64 h35
  text "ARRAY/PANEL:" at 11336.46,2470.64 h35
  text "CUT AND TRIM PER MECH LAYER 1" at 12397.46,2466.35 h35
  text "N.C. ROUTE" at 12397.46,2314.64 h35
  text "X" at 13076.46,2314.64 h35
  text "V. SCORE" at 13263.46,2314.64 h35
  text "CERTIFICATION:" at 11336.46,2177.64 h35
  text "MATERIALS AND WORKMANSHIP FOR ALL PCBS" at 12061.46,2177.64 h35
  text "TO MEET OR EXCEED THE REQUIREMENTS OF:" at 12061.46,2079.64 h35
  text "X" at 11687.96,1943.13 h35
  text "ANSI IPC-A-600F CLASS ->" at 11826.96,1943.13 h35
  text "X" at 13466.02,1943.13 h35
  text "2" at 13584.96,1943.14 h35
  text "1" at 13269.96,1941.64 h35
  text "3" at 13938.96,1941.64 h35
  text "X" at 11690.02,1783.64 h35
  text "UL 94V-0" at 11826.96,1783.64 h35
  text "X" at 12502.02,1783.64 h35
  text "RoHS" at 12638.96,1783.64 h35
  text "OTHER" at 13283.36,1783.64 h35
  text "PER ORDER" at 13680.42,1783.64 h35
  text "ADDITIONAL REQUIREMENTS:" at 11336.46,1642.64 h35
  text "MICROSECTION:" at 11411.23,1527.64 h35
  text "YES" at 12316.96,1527.64 h35
  text "REQUIRED" at 13178.46,1371.49 h35
  text "BARE BOARD ELEC. TEST:" at 11411.23,1368.64 h35
  text "NONE" at 12716.96,1368.64 h35
  text "X" at 13051.46,1368.64 h35
  text "PER ORDER" at 13770.46,1368.64 h35
  text "MANUFACTURER'S UL:" at 11411.23,1211.64 h35
  text "RAIL" at 12576.96,1207.35 h35
  text "METAL" at 13068.77,1207.35 h35
  text "X" at 13444,1207 h35
  text "SILK" at 13580.46,1207.35 h35
  text "VIA`S TO BE TENTED:" at 11391,1020 h35
  text "YES" at 12296,1020 h35
M11 Gerber Information:
  lines w10: -292,-930.17 6308,-930.17 ; -292,-726.83 6310,-726.83 ; -292,-523.5 -292,-1133.5 3713,-1133.5 6310,-1133.5 6310,-523.5 -291.5,-523.5 -291.5,-1133.5 1284,-1133.5 ; 2173,-1133.5 2173,-523.5 ; 3440,-726.83 3440,-523.5 ; 4280,-726.83 4280,-523.5 ; 4902,-1140 4902,-937.17
  text "ALL ARTWORK VIEWED FROM TOP SIDE" at -228.5,-655.67 h35
  text "BOARD #:" at 2248,-655.67 h35
  text ".PRJ_Number" at 2793.5,-655.67 h35
  text "REV:" at 3638,-655.67 h35
  text ".PCB_Rev" at 3929.5,-655.67 h35
  text "SVN REV:" at 4476,-655.67 h35
  text ".VersionControl_RevNumber" at 4982,-655.67 h35
  text "E1" at 3790,-665 h40
  text "LAYER NAME =" at -228.5,-858.49 h35
  text ".plot_File_Name" at 432,-1061 h35
  text "PLOT NAME =" at -228.5,-1064.34 h35
  text "GENERATED    :" at 2250,-1064.34 h35
  text ".Print_Date" at 3119.5,-1064.34 h35
  text ".Print_Time" at 3848.5,-1064.34 h35
  text "TEXAS INSTRUMENTS" at 5113,-1064.34 h35
M12 Stackup:
  lines w6: 11360,7460 13910,7460 ; 11360,7564.4 13910,7564.4 ; 11300,6975 ccw(c11334,6975) 11334,6941 13936,6941 ccw(c13936,6975) 13970,6975 13970,7681 ccw(c13936,7681) 13936,7715 11334,7715 ccw(c11334,7681) 11300,7681 11300,6975
  text "The Stackup Legend below this is static." at 11605.5,7874.5 h35
  text "If you change the stackup, update the Legend." at 11615.5,7784.5 h35
  text "Layer Stack Up Detail for: TIDA-00401.PcbDoc" at 11360,7597.1 h35
  text "Layer" at 11360,7525.4 h35
  text "Gerber" at 12255.81,7525.4 h35
  text "Copper" at 12819.33,7525.4 h35
  text "Dielectric" at 13422.04,7525.4 h35
  text "Name" at 11360,7477.4 h35
  text "Document" at 12255.81,7477.4 h35
  text "Thickness" at 12819.33,7477.4 h35
  text "Material" at 13422.04,7477.4 h35
  text "Top Solder Mask" at 11360,7384.44 h35
  text "(.GTS)" at 12255.81,7384.44 h35
  text "Solder Resist" at 13422.04,7384.44 h35
  text "Top Layer" at 11360,7287.69 h35
  text "(.GTL)" at 12255.81,7287.69 h35
  text "1.4mil" at 12819.33,7287.69 h35
  text "FR-408" at 13422.04,7239.31 h35
  text "Bottom Layer" at 11360,7190.94 h35
  text "(.GBL)" at 12255.81,7190.94 h35
  text "1.4mil" at 12819.33,7190.94 h35
  text "Bottom Solder Mask" at 11360,7094.19 h35
  text "(.GBS)" at 12255.81,7094.19 h35
  text "Solder Resist" at 13422.04,7094.19 h35
M13 Component Bodies Top:
  text ".Layer_Name" at 577,-858.49 h35
M14 Component Bodies Bottom:
  text ".Layer_Name" at 577,-858.49 h35
M15 Courtyards Top:
  text ".Layer_Name" at 577,-858.49 h35
M16 Courtyards Bottom:
  text ".Layer_Name" at 577,-858.49 h35
Drill Drawing:
  text ".legend" at 5122.5,725.5 h35
  text "Drill Table" at 5147.5,540.5 h35
  text ".Layer_Name" at 577,-858.49 h35

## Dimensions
196.85,2165.35 to -133,2362.2 on M2 Board Dimensions
196.85,2165.35 to 0,2442 on M2 Board Dimensions
196.85,196.85 to 0,0 on M2 Board Dimensions
196.85,196.85 to 0,0 on M2 Board Dimensions
3346.46,196.85 to 3543.31,0 on M2 Board Dimensions
3346.46,196.85 to 3543.31,0 on M2 Board Dimensions
3346.46,2165.35 to 3543.31,2362.2 on M2 Board Dimensions
3346.46,2165.35 to 3543.31,2362.2 on M2 Board Dimensions
0,-410.5 to 1000,-410.5 on M2 Board Dimensions
0,0 to 0,2362.2 on M2 Board Dimensions
3543.31,2362.2 to 0,2362 on M2 Board Dimensions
